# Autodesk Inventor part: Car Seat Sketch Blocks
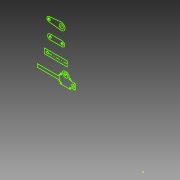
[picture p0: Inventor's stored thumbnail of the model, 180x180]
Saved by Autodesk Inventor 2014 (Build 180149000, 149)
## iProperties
Created: 2008-08
Part Number: Car Seat Sketch Blocks
Document SubType Name: Modeling
Designer: hendert
Density: 1 g/cm^3
Material: Generic
Appearance: Default
d25: 3.346 in
d26: 0.551 in
d27: 0.624 in
d28: 0.354 in
d29: 0.354 in
d30: 0.394 in
d31: 0.354 in
d32: 0.394 in
d33: 0.315 in
d34: 1.811 in
Author: hendert
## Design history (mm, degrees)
node "Blocks"
sketch "Sketch1"
  geometry: L1 (-320.614, 165.364)-(-323.614, 165.364); L2 (-319.614, 166.364)-(-319.614, 171.364); L3 (-318.614, 172.364)-(-313.614, 172.364); L4 (-319.614, 137.364)-(-319.614, 142.364); L5 (-312.614, 136.364)-(-318.614, 136.364); L6 (-312.614, 145.364)-(-312.614, 145.314); L7 (-312.614, 163.414)-(-312.614, 163.364); L8 (-324.614, 164.364)-(-324.614, 144.364); L9 (-323.614, 143.364)-(-320.614, 143.364); L10 (-324.614, 159.128)-(-409.614, 159.128); L11 (-409.614, 159.128)-(-409.614, 147.128); L12 (-409.614, 147.128)-(-324.614, 147.128); L13 (-279.614, 142.364)-(-279.614, 137.364); L14 (-280.614, 136.364)-(-286.614, 136.364); L15 (-312.614, 136.364)-(-286.614, 136.364); L16 (-286.614, 145.314)-(-286.614, 145.364); L17 (-278.614, 143.364)-(-263.614, 143.364); L18 (-263.614, 165.364)-(-278.614, 165.364); L19 (-262.614, 144.364)-(-262.614, 164.364); L20 (-286.614, 173.364)-(-286.614, 177.364); L21 (-296.614, 187.364)-(-302.614, 187.364); L22 (-312.614, 177.364)-(-312.614, 173.364); L23 (-279.614, 171.364)-(-279.614, 166.364); L24 (-285.614, 172.364)-(-280.614, 172.364); L25 (-286.614, 163.364)-(-286.614, 163.414); L26 (-293.608, 225.8)-(-319.608, 225.8); L27 (-293.608, 205.8)-(-293.608, 225.8); L28 (-293.608, 205.8)-(-319.608, 205.8); L29 (-293.608, 215.8)-(-369.905, 215.8); L30 (-381.608, 206.118)-(-381.608, 225.483); L31 (-364.334, 339.782)-(-317.866, 344.754); L32 (-317.866, 316.913)-(-364.334, 321.884); L33 (-359.336, 283.561)-(-313.336, 283.561); L34 (-313.336, 263.561)-(-359.336, 263.561); L35 (-381.608, 225.483)-(-319.608, 225.483); L36 (-319.608, 225.8)-(-319.608, 225.483); L37 (-381.608, 206.118)-(-319.608, 206.118); L38 (-319.608, 205.8)-(-319.608, 206.118); C1 r 1.7 at (-316.114, 168.864); C2 r 1.7 at (-316.114, 139.864); C3 r 1.7 at (-283.114, 139.864); C4 r 6 at (-270.989, 153.128); C5 r 8.5 at (-299.614, 174.364); C6 r 1.7 at (-283.114, 168.864); C7 r 4.5 at (-363.377, 330.833); C8 r 7.92 at (-316.377, 330.833); C9 r 4.5 at (-313.336, 273.561); C10 r 4 at (-359.336, 273.561); A1 r 1 centre (-320.614, 166.364) between (-320.614, 165.364) and (-319.614, 166.364); A2 r 1 centre (-318.614, 171.364) between (-318.614, 172.364) and (-319.614, 171.364); A3 r 1 centre (-320.614, 142.364) between (-319.614, 142.364) and (-320.614, 143.364); A4 r 1 centre (-318.614, 137.364) between (-319.614, 137.364) and (-318.614, 136.364); A5 r 1 centre (-323.614, 144.364) between (-324.614, 144.364) and (-323.614, 143.364); A6 r 1 centre (-323.614, 164.364) between (-323.614, 165.364) and (-324.614, 164.364); A7 r 1 centre (-280.614, 137.364) between (-280.614, 136.364) and (-279.614, 137.364); A8 r 1 centre (-278.614, 142.364) between (-278.614, 143.364) and (-279.614, 142.364); A9 r 1 centre (-263.614, 144.364) between (-263.614, 143.364) and (-262.614, 144.364); A10 r 1 centre (-263.614, 164.364) between (-262.614, 164.364) and (-263.614, 165.364); A11 r 1 centre (-285.614, 173.364) between (-286.614, 173.364) and (-285.614, 172.364); A12 r 10 centre (-296.614, 177.364) between (-286.614, 177.364) and (-296.614, 187.364); A13 r 10 centre (-302.614, 177.364) between (-302.614, 187.364) and (-312.614, 177.364); A14 r 1 centre (-313.614, 173.364) between (-313.614, 172.364) and (-312.614, 173.364); A15 r 1 centre (-280.614, 171.364) between (-279.614, 171.364) and (-280.614, 172.364); A16 r 1 centre (-278.614, 166.364) between (-279.614, 166.364) and (-278.614, 165.364); A17 r 14 centre (-316.377, 330.833) between (-317.866, 316.913) and (-317.866, 344.754); A18 r 9 centre (-363.377, 330.833) between (-364.334, 339.782) and (-364.334, 321.884); A19 r 10 centre (-313.336, 273.561) between (-313.336, 263.561) and (-313.336, 283.561); A20 r 10 centre (-359.336, 273.561) between (-359.336, 283.561) and (-359.336, 263.561); 3 further points
  constraints: 76 end point, 40 point on circle, 30 centre point, 8 tangent, 5 perpendicular, 4 concentric, 2 horizontal alignment, 2 parallel, 2 point on line, 1 midpoint, 1 other
  dimensions: "d25" = 85 distance between parallel lines of L8 L11; "d26" = 14 radius of A17; "d27" = 15.84 diameter of C8; "d28" = 9 diameter of C7; "d29" = 9 radius of A18; "d30" = 10 radius of A19; "d31" = 9 diameter of C9; "d32" = 10 radius of A20; "d33" = 8 diameter of C10; "d34" = 46 distance of C9.centre C10.centre
